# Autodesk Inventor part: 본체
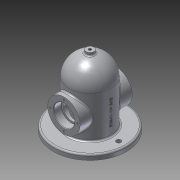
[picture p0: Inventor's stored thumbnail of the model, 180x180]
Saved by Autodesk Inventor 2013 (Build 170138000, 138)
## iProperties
Created: 2019-11
Part Number: 본체
Material: 알루미늄 6061
Document SubType Name: Modeling
Designer: Administrator
Density: 2.71 g/cm^3
Mass: 1110.07 g
Surface Area: 883.581 cm^2
Volume: 409.619 cm^3
Author: Administrator
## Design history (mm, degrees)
sketch "스케치4"
  geometry: C1 r 40 at (0, 0); 1 further point
  constraints: 1 centre point, 1 coincident
  dimensions: "d5" = 80 diameter of C1
extrude "돌출1" new body sketch "스케치4" distance "d7" = 90; taper "d8" = 0 deg
sketch "스케치5"
  geometry: L1 (-40, 0)-(-40, 90) reference; L2 (40, 90)-(-40, 90) reference; L3 (-40, 90)-(40, 90); L4 (40, 0)-(40, 90) reference; L5 (0, 0)-(0, 90); A1 r 40 centre (0, 90) between (40, 90) and (-40, 90)
  constraints: 6 end point, 3 point on circle, 2 point on line, 1 centre point, 1 coincident, 1 midpoint
revolve "회전1" sketch "스케치5" stored, may be unused: angle "d9" = 90 deg
sketch "스케치6"
  geometry: C1 r 40 at (0, 0) reference
feature "쉘1" dims "d10" = 10
sketch "스케치7"
  geometry: C1 r 40 at (0, 0); C2 r 70 at (0, 0); 1 further point
  constraints: 2 centre point, 2 coincident
  dimensions: "d13" = 80 diameter of C1; "d15" = 140 diameter of C2
extrude "돌출2" join sketch "스케치7" distance "d16" = 10; taper "d17" = 0 deg
node "작업 평면1"
sketch "스케치13"
  geometry: C1 r 7.5 at (0, 0); 1 further point
  constraints: 1 centre point, 1 coincident
  dimensions: "d38" = 15 diameter of C1
extrude "돌출5" join sketch "스케치13" stored distance "d40" = 15; taper "d41" = 0 deg
sketch "스케치14"
  geometry: C1 r 7.5 at (0, 0) reference
hole "구멍1" sketch "스케치14" at (0, 0) diameter "d42" = 5.188; stored, may be unused: countersink angle "d46" = 90 deg, drill point angle "d48" = 118 deg; dims "d43" = 6, "d44" = 4, "d45" = 2, "d47" = 8
node "작업 평면2"
sketch "스케치20"
  geometry: L1 (0, 0)-(0, 50); L2 (30, 0)-(-30, 0) reference; C1 r 31 at (0, 50)
  constraints: 2 end point, 1 centre point, 1 coincident, 1 perpendicular
  dimensions: "d61" = 50 distance of L1.start L1.end; "d62" = 62 diameter of C1
extrude "돌출6" join sketch "스케치20" stored distance "d63" = 15; taper "d64" = 0 deg
fillet "모깎기2" dims "d65" = 3
sketch "스케치21"
  geometry: C1 r 31 at (0, 0) reference; C2 r 20 at (0, 0); 1 further point
  constraints: 1 centre point, 1 coincident
  dimensions: "d66" = 40 diameter of C2
extrude "돌출7" cut sketch "스케치21" distance "d68" = 15; taper "d69" = 0 deg
sketch "스케치22"
  geometry: C1 r 20 at (0, 0) reference; C2 r 16.5 at (0, 0); 1 further point
  constraints: 1 centre point, 1 coincident
  dimensions: "d70" = 33 diameter of C2
extrude "돌출8" cut sketch "스케치22" stored distance "d72" = 15; taper "d73" = 0 deg
fillet "모깎기3" dims "d74" = 3
fillet "모깎기4" dims "d75" = 0.3
chamfer "모따기3" distance "d76" = 1; stored, may be unused: second distance "d77" = 2, angle "d78" = 45 deg
chamfer "모따기4" distance "d79" = 1; stored, may be unused: second distance "d80" = 2, angle "d81" = 45 deg
sketch "스케치23"
  geometry: L1 (0, 0)-(0, 26); C1 r 21 at (0, 0) reference; 1 further point
  constraints: 2 end point, 1 vertical
  dimensions: "d82" = 26 distance of L1.start L1.end
hole "구멍3" sketch "스케치23" at (0, 26) diameter "d83" = 3.242; stored, may be unused: countersink angle "d87" = 82 deg, drill point angle "d89" = 118 deg; dims "d84" = 8, "d85" = 3.023, "d86" = 2, "d88" = 10
fillet "모깎기5" dims "d93" = 3
sketch "스케치25"
  geometry: L1 (0, 0)-(55, 0); C1 r 43 at (0, 0) reference; C2 r 4.5 at (55, 0)
  constraints: 2 end point, 1 centre point, 1 coincident, 1 horizontal
  dimensions: "d94" = 55 distance of L1.start L1.end; "d95" = 9 diameter of C2
extrude "돌출9" cut sketch "스케치25" stored distance "d96" = 15; taper "d97" = 0 deg
node "작업 평면4"
sketch "스케치26"
  geometry: L1 (-70, 0)-(70, 0) reference; 2 further points
  constraints: 1 vertical alignment, 1 other
  dimensions: "d103" = 50 distance from line of L1 point (0, 50)
feature "엠보싱1" sketch "스케치26" dims "d104" = 0.5, "d105" = 0
fillet "모깎기6" dims "d106" = 3
node "솔리드1"
mirror "대칭4"
pattern_circular "원형 패턴2" dims angle "d91" = 360 deg
mirror "대칭5"
pattern_circular "원형 패턴3" dims angle "d99" = 360 deg
other parameters: "d37" = 135, "d102" = 62
